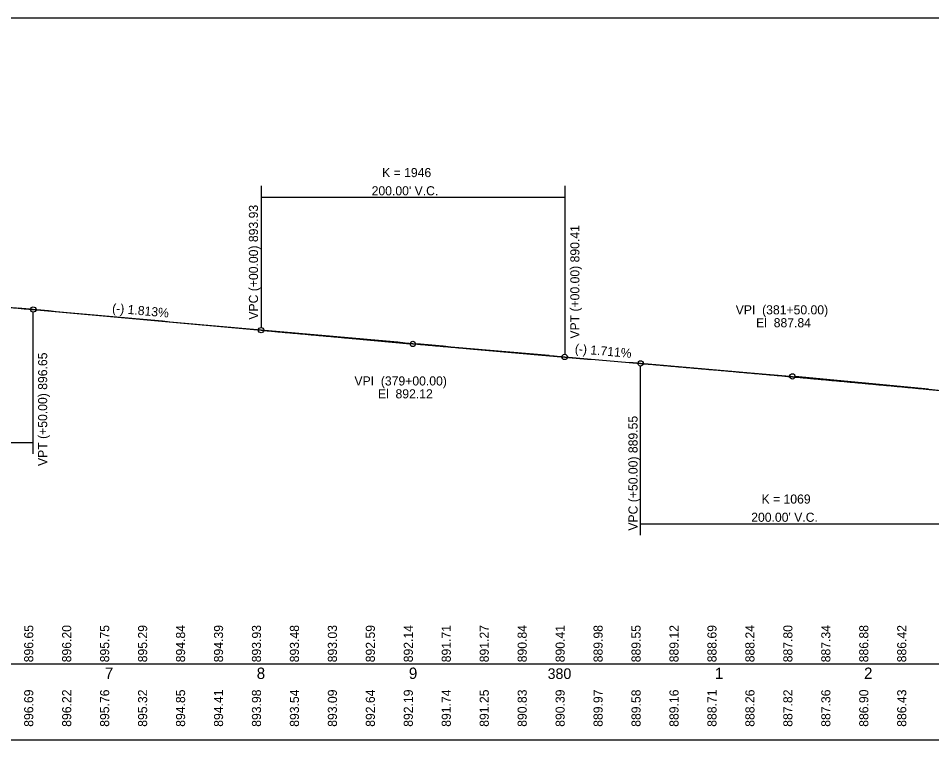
# Model space of a CAD drawing. Extents: x 4180 to 16997695, y 4 to 12629821.
# Drawn here: x 16990060 to 16990662, y 12626738 to 12627213 of the extents above; entities that cross this region are included whole.
import ezdxf

# ---------------------------------------------------------------- set-up
doc = ezdxf.new("R2010")
doc.units = 0
for name, color, linetype in [('Default', 7, 'Continuous'), ('RD_DDB_GradeTX', 7, 'Continuous'), ('RD_DDB_PI', 7, 'Continuous'), ('RD_DDB_Profile_EX', 7, 'Continuous'), ('RD_DDB_Profile_PR', 7, 'Continuous'), ('RD_DDB_StaTX', 7, 'Continuous'), ('RD_DDB_StripGrade', 7, 'Continuous'), ('RD_DDB_StripGrade_PR', 7, 'Continuous'), ('RD_DDB_VCLbl', 7, 'Continuous'), ('RD_GPK_Profile_Cell', 7, 'Continuous')]:
    doc.layers.add(name, color=color, linetype=linetype)

msp = doc.modelspace()

# ---------------------------------------------------------------- linework, layer by layer
at = {"layer": 'Default'}
msp.add_lwpolyline([(16989719.88, 12626737.79), (16991219.88, 12626737.79), (16991219.88, 12627212.79), (16989719.88, 12627212.79)], close=True, dxfattribs=at)
at = {"layer": 'RD_DDB_PI'}
for p, q in [((16990230.24, 12627006.51), (16990318.13, 12626998.54)), ((16990409.55, 12626990.71), (16990321.62, 12626998.23)), ((16990480.2, 12626984.67), (16990568.13, 12626977.15)), ((16990659.47, 12626968.5), (16990571.62, 12626976.84))]:
    msp.add_line(p, q, dxfattribs=at)
for centre in [(16990319.88, 12626998.38), (16990569.88, 12626977)]:
    msp.add_circle(centre, 1.75, dxfattribs=at)
at = {"layer": 'RD_DDB_Profile_EX'}
for points in [[(16990059.88, 12627022.13), (16990064.88, 12627021.68), (16990069.88, 12627021.23), (16990074.88, 12627020.77), (16990079.88, 12627020.29), (16990084.88, 12627019.81), (16990089.88, 12627019.33), (16990094.88, 12627018.87), (16990099.88, 12627018.41), (16990104.88, 12627017.96), (16990109.88, 12627017.51), (16990114.88, 12627017.06), (16990119.88, 12627016.6)], [(16990119.88, 12627016.6), (16990124.88, 12627016.14), (16990129.88, 12627015.71), (16990134.88, 12627015.27), (16990139.88, 12627014.83), (16990144.88, 12627014.39), (16990149.88, 12627013.94), (16990154.88, 12627013.48), (16990159.88, 12627013.02), (16990164.88, 12627012.55), (16990169.88, 12627012.05), (16990174.88, 12627011.54), (16990179.88, 12627011.11), (16990184.88, 12627010.69), (16990189.88, 12627010.26), (16990194.88, 12627009.84), (16990199.88, 12627009.42), (16990204.88, 12627009), (16990209.88, 12627008.58), (16990214.88, 12627008.15), (16990219.88, 12627007.69), (16990224.88, 12627007.21), (16990229.88, 12627006.75), (16990234.88, 12627006.34), (16990239.88, 12627005.92), (16990244.88, 12627005.5), (16990249.88, 12627005.06), (16990254.88, 12627004.6), (16990259.88, 12627004.13), (16990264.88, 12627003.66), (16990269.88, 12627003.23), (16990274.88, 12627002.8), (16990279.88, 12627002.37), (16990284.88, 12627001.93), (16990289.88, 12627001.47), (16990294.88, 12627001), (16990299.88, 12627000.53), (16990304.88, 12627000.09), (16990309.88, 12626999.65), (16990314.88, 12626999.21), (16990319.88, 12626998.76), (16990324.88, 12626998.35), (16990329.88, 12626997.94), (16990334.88, 12626997.53), (16990339.88, 12626997.03), (16990344.88, 12626996.49), (16990349.88, 12626995.95), (16990354.88, 12626995.41), (16990359.88, 12626994.95), (16990364.88, 12626994.49), (16990369.88, 12626994.03), (16990374.88, 12626993.59), (16990379.88, 12626993.18), (16990384.88, 12626992.76), (16990389.88, 12626992.34), (16990394.88, 12626991.92), (16990399.88, 12626991.49), (16990404.88, 12626991.05), (16990409.88, 12626990.62), (16990414.88, 12626990.18), (16990419.88, 12626989.75), (16990424.88, 12626989.31), (16990429.88, 12626988.87), (16990434.88, 12626988.43), (16990439.88, 12626988.04), (16990444.88, 12626987.64), (16990449.88, 12626987.25), (16990454.88, 12626986.85), (16990459.88, 12626986.47), (16990464.88, 12626986.09), (16990469.88, 12626985.7), (16990474.88, 12626985.3), (16990479.88, 12626984.88), (16990484.88, 12626984.46), (16990489.88, 12626984.04), (16990494.88, 12626983.6), (16990499.88, 12626983.15), (16990504.88, 12626982.7), (16990509.88, 12626982.26), (16990514.88, 12626981.81), (16990519.88, 12626981.36), (16990524.88, 12626980.9), (16990529.88, 12626980.44), (16990534.88, 12626979.97), (16990539.88, 12626979.51), (16990544.88, 12626979.1), (16990549.88, 12626978.67), (16990554.88, 12626978.25), (16990559.88, 12626977.8), (16990564.88, 12626977.34), (16990569.88, 12626976.88), (16990574.88, 12626976.42), (16990579.88, 12626975.96), (16990584.88, 12626975.49), (16990589.88, 12626975.05), (16990594.88, 12626974.61), (16990599.88, 12626974.17), (16990604.88, 12626973.72), (16990609.88, 12626973.25), (16990614.88, 12626972.78), (16990619.88, 12626972.3)], [(16990619.88, 12626972.3), (16990624.88, 12626971.82), (16990629.88, 12626971.36), (16990634.88, 12626970.89), (16990639.88, 12626970.42), (16990644.88, 12626969.94), (16990649.88, 12626969.44), (16990654.88, 12626968.95), (16990659.88, 12626968.45), (16990664.88, 12626967.95)]]:
    msp.add_lwpolyline(points, dxfattribs=at)
at = {"layer": 'RD_DDB_Profile_PR'}
for p, q in [((16990069.88, 12627021.05), (16990219.88, 12627007.45)), ((16990419.88, 12626989.83), (16990469.88, 12626985.55))]:
    msp.add_line(p, q, dxfattribs=at)
for points in [[(16989869.88, 12627038.64), (16989873.88, 12627038.3), (16989877.88, 12627037.96), (16989881.88, 12627037.62), (16989885.88, 12627037.28), (16989889.88, 12627036.93), (16989893.88, 12627036.59), (16989897.88, 12627036.25), (16989901.88, 12627035.9), (16989905.88, 12627035.56), (16989909.88, 12627035.21), (16989913.88, 12627034.87), (16989917.88, 12627034.52), (16989921.88, 12627034.17), (16989925.88, 12627033.83), (16989929.88, 12627033.48), (16989933.88, 12627033.13), (16989937.88, 12627032.78), (16989941.88, 12627032.44), (16989945.88, 12627032.09), (16989949.88, 12627031.74), (16989953.88, 12627031.39), (16989957.88, 12627031.04), (16989961.88, 12627030.69), (16989965.88, 12627030.33), (16989969.88, 12627029.98), (16989973.88, 12627029.63), (16989977.88, 12627029.28), (16989981.88, 12627028.93), (16989985.88, 12627028.57), (16989989.88, 12627028.22), (16989993.88, 12627027.86), (16989997.88, 12627027.51), (16990001.88, 12627027.15), (16990005.88, 12627026.8), (16990009.88, 12627026.44), (16990013.88, 12627026.09), (16990017.88, 12627025.73), (16990021.88, 12627025.37), (16990025.88, 12627025.01), (16990029.88, 12627024.66), (16990033.88, 12627024.3), (16990037.88, 12627023.94), (16990041.88, 12627023.58), (16990045.88, 12627023.22), (16990049.88, 12627022.86), (16990053.88, 12627022.5), (16990057.88, 12627022.14), (16990061.88, 12627021.78), (16990065.88, 12627021.41), (16990069.88, 12627021.05)], [(16990219.88, 12627007.45), (16990223.88, 12627007.09), (16990227.88, 12627006.73), (16990231.88, 12627006.36), (16990235.88, 12627006), (16990239.88, 12627005.64), (16990243.88, 12627005.28), (16990247.88, 12627004.92), (16990251.88, 12627004.56), (16990255.88, 12627004.2), (16990259.88, 12627003.84), (16990263.88, 12627003.49), (16990267.88, 12627003.13), (16990271.88, 12627002.77), (16990275.88, 12627002.41), (16990279.88, 12627002.06), (16990283.88, 12627001.7), (16990287.88, 12627001.34), (16990291.88, 12627000.99), (16990295.88, 12627000.63), (16990299.88, 12627000.28), (16990303.88, 12626999.92), (16990307.88, 12626999.57), (16990311.88, 12626999.22), (16990315.88, 12626998.86), (16990319.88, 12626998.51), (16990323.88, 12626998.16), (16990327.88, 12626997.81), (16990331.88, 12626997.46), (16990335.88, 12626997.11), (16990339.88, 12626996.76), (16990343.88, 12626996.4), (16990347.88, 12626996.06), (16990351.88, 12626995.71), (16990355.88, 12626995.36), (16990359.88, 12626995.01), (16990363.88, 12626994.66), (16990367.88, 12626994.31), (16990371.88, 12626993.97), (16990375.88, 12626993.62), (16990379.88, 12626993.27), (16990383.88, 12626992.93), (16990387.88, 12626992.58), (16990391.88, 12626992.24), (16990395.88, 12626991.89), (16990399.88, 12626991.55), (16990403.88, 12626991.2), (16990407.88, 12626990.86), (16990411.88, 12626990.52), (16990415.88, 12626990.17), (16990419.88, 12626989.83)], [(16990469.88, 12626985.55), (16990473.88, 12626985.21), (16990477.88, 12626984.87), (16990481.88, 12626984.52), (16990485.88, 12626984.18), (16990489.88, 12626983.83), (16990493.88, 12626983.49), (16990497.88, 12626983.14), (16990501.88, 12626982.79), (16990505.88, 12626982.44), (16990509.88, 12626982.09), (16990513.88, 12626981.74), (16990517.88, 12626981.39), (16990521.88, 12626981.04), (16990525.88, 12626980.69), (16990529.88, 12626980.34), (16990533.88, 12626979.98), (16990537.88, 12626979.63), (16990541.88, 12626979.27), (16990545.88, 12626978.92), (16990549.88, 12626978.56), (16990553.88, 12626978.2), (16990557.88, 12626977.85), (16990561.88, 12626977.49), (16990565.88, 12626977.13), (16990569.88, 12626976.77), (16990573.88, 12626976.41), (16990577.88, 12626976.04), (16990581.88, 12626975.68), (16990585.88, 12626975.32), (16990589.88, 12626974.95), (16990593.88, 12626974.59), (16990597.88, 12626974.22), (16990601.88, 12626973.86), (16990605.88, 12626973.49), (16990609.88, 12626973.12), (16990613.88, 12626972.75), (16990617.88, 12626972.38), (16990621.88, 12626972.01), (16990625.88, 12626971.64), (16990629.88, 12626971.27), (16990633.88, 12626970.9), (16990637.88, 12626970.52), (16990641.88, 12626970.15), (16990645.88, 12626969.78), (16990649.88, 12626969.4), (16990653.88, 12626969.02), (16990657.88, 12626968.65), (16990661.88, 12626968.27), (16990665.88, 12626967.89), (16990669.88, 12626967.51)]]:
    msp.add_spline(points, degree=3, dxfattribs=at)
at = {"layer": 'RD_DDB_VCLbl'}
for p, q in [((16990219.88, 12627102.45), (16990219.88, 12627009.2)), ((16990419.88, 12627102.45), (16990419.88, 12626991.58)), ((16990219.88, 12627094.95), (16990419.88, 12627094.95)), ((16990069.88, 12626926.05), (16990069.88, 12627019.3)), ((16990469.88, 12626872.51), (16990469.88, 12626983.8)), ((16989869.88, 12626933.55), (16990069.88, 12626933.55)), ((16990469.88, 12626880.01), (16990669.88, 12626880.01))]:
    msp.add_line(p, q, dxfattribs=at)
for centre in [(16990069.88, 12627021.05), (16990219.88, 12627007.45), (16990419.88, 12626989.83), (16990469.88, 12626985.55)]:
    msp.add_circle(centre, 1.75, dxfattribs=at)
at = {"layer": 'RD_GPK_Profile_Cell'}
msp.add_line((16972619.88, 12626787.79), (16997196.51, 12626787.79), dxfattribs=at)

# ---------------------------------------------------------------- texts
at = {"layer": 'RD_DDB_GradeTX'}
for s, rotation, p in [('(-) 1.813%', 354.81914, (16990121.61, 12627019.11)), ('(-) 1.711%', 355.11125, (16990426.37, 12626992.39))]:
    msp.add_text(s, height=6, rotation=rotation, dxfattribs=at).set_placement(p)
at = {"layer": 'RD_DDB_PI'}
for s, p in [('VPI  (381+50.00)', (16990532.52, 12627017.83)), ('El  887.84', (16990545.96, 12627009.33)), ('VPI  (379+00.00)', (16990281.4, 12626971.02)), ('El  892.12', (16990296.87, 12626962.52))]:
    msp.add_text(s, height=6, dxfattribs=at).set_placement(p)
at = {"layer": 'RD_DDB_StaTX'}
for s, height, p in [('7', 7.5, (16990117, 12626777.79)), ('8', 7.5, (16990217.03, 12626777.79)), ('9', 7.5, (16990317.23, 12626777.79)), ('380', 7, (16990408.63, 12626777.79)), ('1', 7.5, (16990518.87, 12626777.79)), ('2', 7.5, (16990617.03, 12626777.79))]:
    msp.add_text(s, height=height, dxfattribs=at).set_placement(p)
at = {"layer": 'RD_DDB_StripGrade'}
for s, p in [('896.69', (16990069.88, 12626746.3)), ('896.22', (16990094.88, 12626746.3)), ('895.76', (16990119.88, 12626746.3)), ('895.32', (16990144.88, 12626746.3)), ('894.85', (16990169.88, 12626746.3)), ('894.41', (16990194.88, 12626746.3)), ('893.98', (16990219.88, 12626746.3)), ('893.54', (16990244.88, 12626746.3)), ('893.09', (16990269.88, 12626746.3)), ('892.64', (16990294.88, 12626746.3)), ('892.19', (16990319.88, 12626746.3)), ('891.74', (16990344.88, 12626746.3)), ('891.25', (16990369.88, 12626746.3)), ('890.83', (16990394.88, 12626746.3)), ('890.39', (16990419.88, 12626746.3)), ('889.97', (16990444.88, 12626746.3)), ('889.58', (16990469.88, 12626746.3)), ('889.16', (16990494.88, 12626746.3)), ('888.71', (16990519.88, 12626746.3)), ('888.26', (16990544.88, 12626746.3)), ('887.82', (16990569.88, 12626746.3)), ('887.36', (16990594.88, 12626746.3)), ('886.90', (16990619.88, 12626746.3)), ('886.43', (16990644.88, 12626746.3))]:
    msp.add_text(s, height=6, rotation=90, dxfattribs=at).set_placement(p)
at = {"layer": 'RD_DDB_StripGrade_PR'}
for s, p in [('896.65', (16990069.88, 12626788.77)), ('896.20', (16990094.88, 12626788.77)), ('895.75', (16990119.88, 12626788.77)), ('895.29', (16990144.88, 12626788.77)), ('894.84', (16990169.88, 12626788.77)), ('894.39', (16990194.88, 12626788.77)), ('893.93', (16990219.88, 12626788.77)), ('893.48', (16990244.88, 12626788.77)), ('893.03', (16990269.88, 12626788.77)), ('892.59', (16990294.88, 12626788.77)), ('892.14', (16990319.88, 12626788.77)), ('891.71', (16990344.88, 12626788.77)), ('891.27', (16990369.88, 12626788.77)), ('890.84', (16990394.88, 12626788.77)), ('890.41', (16990419.88, 12626788.77)), ('889.98', (16990444.88, 12626788.77)), ('889.55', (16990469.88, 12626788.77)), ('889.12', (16990494.88, 12626788.77)), ('888.69', (16990519.88, 12626788.77)), ('888.24', (16990544.88, 12626788.77)), ('887.80', (16990569.88, 12626788.77)), ('887.34', (16990594.88, 12626788.77)), ('886.88', (16990619.88, 12626788.77)), ('886.42', (16990644.88, 12626788.77))]:
    msp.add_text(s, height=6, rotation=90, dxfattribs=at).set_placement(p)
at = {"layer": 'RD_DDB_VCLbl'}
for s, p in [('K = 1946', (16990299.62, 12627108.2)), ("200.00' V.C.", (16990292.74, 12627096.2)), ('K = 1069', (16990549.51, 12626893.26)), ("200.00' V.C.", (16990542.74, 12626881.26))]:
    msp.add_text(s, height=6, dxfattribs=at).set_placement(p)
for s, p in [('VPC (+00.00) 893.93', (16990217.88, 12627014.35)), ('VPT (+00.00) 890.41', (16990429.57, 12627001.88)), ('VPT (+50.00) 896.65', (16990079.03, 12626918)), ('VPC (+50.00) 889.55', (16990467.88, 12626875.43))]:
    msp.add_text(s, height=6, rotation=90, dxfattribs=at).set_placement(p)

doc.saveas('drawing.dxf')
